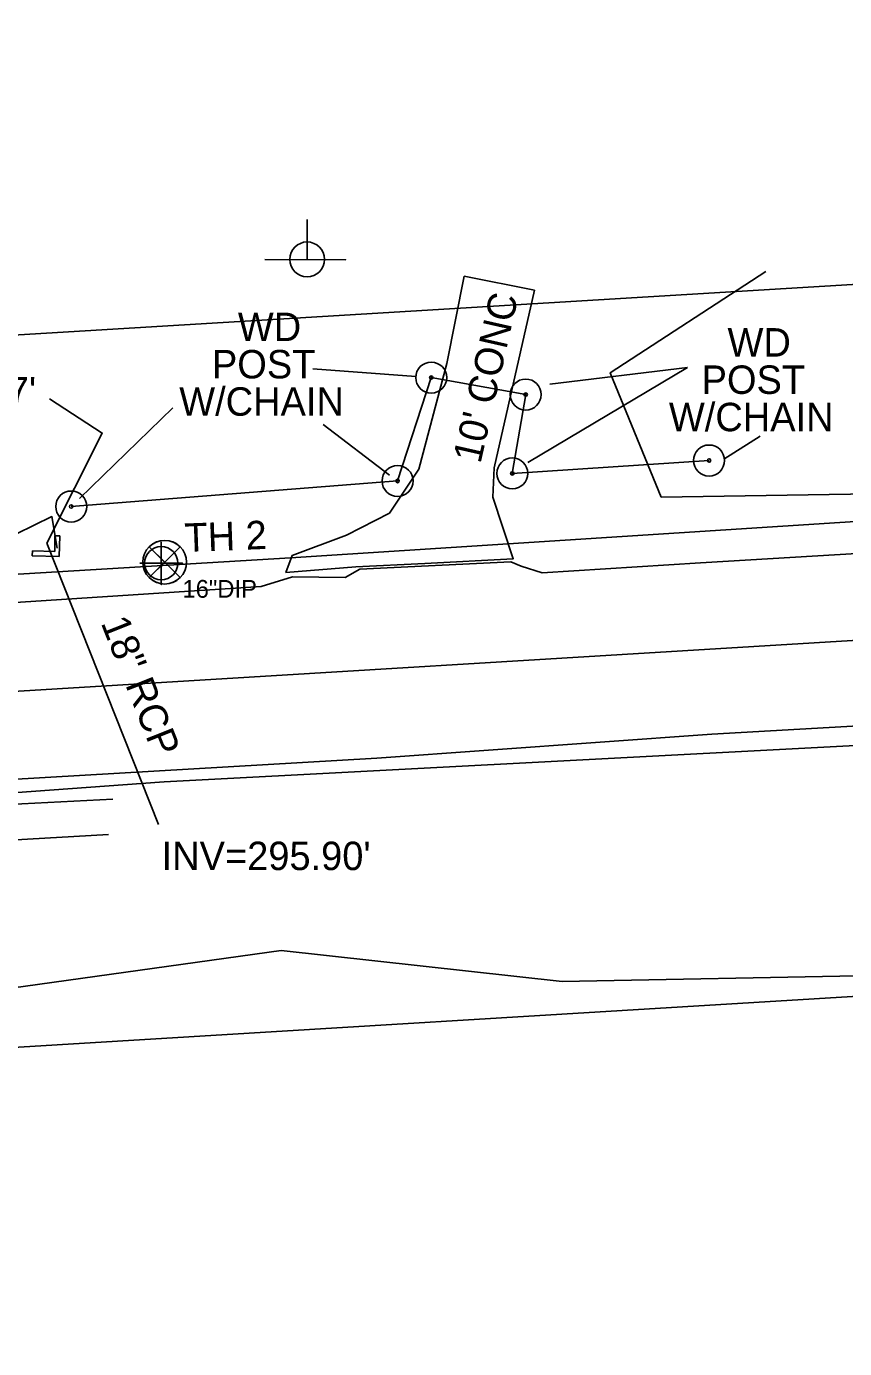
# Model space of a CAD drawing. Extents: x 2110969 to 2113691, y 670003 to 672285.
# Drawn here: x 2112976.4 to 2113091.6, y 670433.2 to 670619.2 of the extents above; entities that cross this region are included whole.
import ezdxf

# ---------------------------------------------------------------- set-up
doc = ezdxf.new("R2010")
doc.units = 0
for name, color, linetype in [('Exist DTM Regular Point CELL', 7, 'Continuous'), ('Exist Horizontal Alignment', 7, 'Continuous'), ('Exist Other Culture Fence Line', 7, 'Continuous'), ('Exist Other Culture Located Object CELL', 7, 'Continuous'), ('Exist Other Culture Located Object Leader', 7, 'Continuous'), ('Exist Other Culture Located Object Text', 7, 'Continuous'), ('Exist Right of Way Line', 7, 'Continuous'), ('Exist Roads EOP', 7, 'Continuous'), ('Exist Roads EOP Other', 7, 'Continuous'), ('Exist Roads EOP Other Text', 7, 'Continuous'), ('Exist Structure Minor Head and End Wall', 7, 'Continuous'), ('Exist Structure Minor Paved Ditch or Gutter', 7, 'Continuous'), ('Exist Structure Minor Pipes RCP 18 Inch', 7, 'Continuous'), ('Exist Structure Minor Pipes RCP 18 Inch Invert', 7, 'Continuous'), ('Exist Structure Minor Pipes RCP 18 Inch Leader', 7, 'Continuous'), ('Exist Structure Minor Pipes RCP 18 Inch Text', 7, 'Continuous'), ('Exist Utilities Power Joint Use Telephone CELL', 7, 'Continuous'), ('Exist Utilities Telephone UG FO SUE LOS B', 7, 'Continuous'), ('Exist Utilities Water Test Hole SUE LOS A CELL', 7, 'Continuous'), ('Exist Utilities Water Test Hole SUE LOS A Cogo Comment', 7, 'Continuous'), ('Exist Utilities Water Test Hole SUE LOS A Text', 7, 'Continuous'), ('Exist Utilities Water UG Line SUE LOS B', 7, 'Continuous'), ('Exist Vegetation Woods Line', 7, 'Continuous')]:
    doc.layers.add(name, color=color, linetype=linetype)

msp = doc.modelspace()

# ---------------------------------------------------------------- linework, layer by layer
at = {"layer": 'Exist DTM Regular Point CELL'}
msp.add_lwpolyline([(2112995.39, 670546.67), (2112995.39, 670540.67), (2112995.39, 670543.67), (2112998.39, 670543.67), (2112992.39, 670543.67)], dxfattribs=at)
msp.add_circle((2112995.39, 670543.67), 2.34, dxfattribs=at)
at = {"layer": 'Exist Horizontal Alignment'}
msp.add_line((2111597.13, 670442.15), (2113362.13, 670549.12), dxfattribs=at)
at = {"layer": 'Exist Other Culture Fence Line'}
msp.add_lwpolyline([(2112982.71, 670551.64), (2113028.65, 670555.23), (2113033.39, 670569.77), (2113046.68, 670567.38), (2113044.8, 670556.3), (2113072.49, 670558.11)], dxfattribs=at)
at = {"layer": 'Exist Other Culture Located Object CELL'}
for centre, radius in [((2113033.39, 670569.77), 2.18), ((2113033.39, 670569.77), 0.24), ((2113046.68, 670567.38), 2.18), ((2113046.68, 670567.38), 0.24), ((2113072.49, 670558.11), 2.18), ((2113028.65, 670555.23), 2.18), ((2113044.8, 670556.3), 2.18), ((2113072.49, 670558.11), 0.24), ((2113044.8, 670556.3), 0.24), ((2112982.71, 670551.64), 2.18), ((2113028.65, 670555.23), 0.24), ((2112982.71, 670551.64), 0.24)]:
    msp.add_circle(centre, radius, dxfattribs=at)
at = {"layer": 'Exist Other Culture Located Object Leader'}
for p, q in [((2113031.21, 670569.94), (2113016.71, 670571.02)), ((2113046.96, 670557.82), (2113069.46, 670571.18)), ((2113050.06, 670568.85), (2113069.46, 670571.18)), ((2112983.89, 670552.78), (2112997, 670565.51)), ((2113027.49, 670556.04), (2113018.18, 670563.18)), ((2113074.58, 670558.29), (2113079.69, 670561.55))]:
    msp.add_line(p, q, dxfattribs=at)
at = {"layer": 'Exist Right of Way Line'}
for p, q in [((2112826.13, 670566.73), (2113691.32, 670619.17)), ((2112275.95, 670433.2), (2113479.86, 670506.17))]:
    msp.add_line(p, q, dxfattribs=at)
at = {"layer": 'Exist Roads EOP'}
for points in [[(2113361.19, 670561.38), (2113300, 670557.8), (2113237.06, 670554.42), (2113180.42, 670550.57), (2113120.04, 670546.64), (2113071.3, 670543.72), (2113048.98, 670542.29), (2113046.06, 670543.23), (2113044.6, 670543.86), (2113023.33, 670542.83), (2113021.27, 670541.64), (2113013.84, 670541.76), (2113009.46, 670540.39), (2112955.35, 670536.89), (2112893.42, 670532.66), (2112858.8, 670530.45), (2112800.17, 670526.96), (2112780.32, 670525.95), (2112776.24, 670526.52)], [(2113362.39, 670537.44), (2113297.78, 670533.58), (2113239.25, 670529.55), (2113180.88, 670526), (2113122.41, 670522.43), (2113072.9, 670519.62), (2113025.73, 670516.23), (2112958.1, 670512.29), (2112895.8, 670508.35), (2112861.36, 670506), (2112803.82, 670502.84), (2112777.04, 670501.11)]]:
    msp.add_lwpolyline(points, dxfattribs=at)
at = {"layer": 'Exist Roads EOP Other'}
msp.add_lwpolyline([(2113038.02, 670584.04), (2113047.91, 670582.05), (2113042.26, 670557.1), (2113042.04, 670552.97), (2113044.92, 670544.3), (2113032.48, 670543.61), (2113022.79, 670543.16), (2113012.94, 670542.38), (2113013.82, 670544.76), (2113021.45, 670547.6), (2113027.51, 670550.72), (2113031.64, 670556.88), (2113035.59, 670571.75), (2113038.02, 670584.04)], dxfattribs=at)
at = {"layer": 'Exist Structure Minor Head and End Wall'}
for p, q in [((2112981.12, 670547.52), (2112980.41, 670547.51)), ((2112980.43, 670545.32), (2112980.41, 670547.51)), ((2112981.12, 670547.52), (2112981.04, 670544.59)), ((2112977.23, 670544.69), (2112977.26, 670545.4)), ((2112977.24, 670544.69), (2112981.04, 670544.59)), ((2112977.26, 670545.4), (2112980.43, 670545.32))]:
    msp.add_line(p, q, dxfattribs=at)
at = {"layer": 'Exist Structure Minor Paved Ditch or Gutter'}
for points in [[(2112886.95, 670541.73), (2112937.79, 670544.35), (2112973.54, 670547.17), (2112975.01, 670547.8), (2112979.99, 670550.22), (2112980.72, 670545.78)], [(2112988.55, 670510.48), (2112937.28, 670507.84), (2112884.19, 670504.54), (2112819.22, 670500.65), (2112761.65, 670497.03), (2112707.07, 670494.25), (2112651.72, 670490.01)], [(2112987.94, 670505.51), (2112937.44, 670502.6), (2112883.37, 670499.77), (2112819.5, 670495.9), (2112761.24, 670491.77), (2112707.32, 670488.73), (2112652.43, 670485.21)]]:
    msp.add_lwpolyline(points, dxfattribs=at)
at = {"layer": 'Exist Structure Minor Pipes RCP 18 Inch'}
msp.add_line((2112979.28, 670546.47), (2112994.98, 670506.91), dxfattribs=at)
at = {"layer": 'Exist Structure Minor Pipes RCP 18 Inch Leader'}
msp.add_lwpolyline([(2112979.28, 670546.47), (2112987.09, 670561.98), (2112979.66, 670566.79)], dxfattribs=at)
at = {"layer": 'Exist Utilities Power Joint Use Telephone CELL'}
msp.add_line((2113015.92, 670586.39), (2113015.92, 670586.39), dxfattribs=at)
msp.add_lwpolyline([(2113009.98, 670586.39), (2113021.32, 670586.35), (2113015.92, 670586.37), (2113015.92, 670592.02)], dxfattribs=at)
msp.add_circle((2113015.92, 670586.4), 2.45, dxfattribs=at)
at = {"layer": 'Exist Utilities Telephone UG FO SUE LOS B'}
msp.add_lwpolyline([(2112667.68, 670491.25), (2112816.71, 670501.11), (2112922.17, 670507.55), (2112995.79, 670512.91), (2113269.89, 670527.3)], dxfattribs=at)
msp.add_lwpolyline([(2112667.68, 670491.25), (2112816.71, 670501.11), (2112922.17, 670507.55), (2112995.79, 670512.91), (2113269.89, 670527.3)], dxfattribs=at)
at = {"layer": 'Exist Utilities Water Test Hole SUE LOS A CELL'}
for points in [[(2112998.04, 670545.99), (2112993.69, 670541.64), (2112995.87, 670543.81), (2112993.69, 670545.99), (2112998.04, 670541.64)], [(2112993.69, 670545.99), (2112995.87, 670543.81), (2112998.04, 670545.99)], [(2112998.04, 670541.64), (2112995.87, 670543.81), (2112993.69, 670541.64)]]:
    msp.add_lwpolyline(points, dxfattribs=at)
msp.add_circle((2112995.87, 670543.81), 3.07, dxfattribs=at)
for start, end in [(45, 135), (225, 315)]:
    msp.add_arc((2112995.87, 670543.81), 3.07, start, end, dxfattribs=at)
at = {"layer": 'Exist Utilities Water UG Line SUE LOS B'}
msp.add_lwpolyline([(2112063.12, 670452.82), (2112061.08, 670490.25), (2112149, 670492.87), (2112291.17, 670500.39), (2112417.24, 670508.2), (2112519.46, 670514.32), (2112696.23, 670524.3), (2112788.03, 670530.3), (2112902.5, 670537.78), (2113013.6, 670544.43), (2113214.88, 670557.36), (2113313.23, 670563.26)], dxfattribs=at)
msp.add_lwpolyline([(2112063.12, 670452.82), (2112061.08, 670490.25), (2112149, 670492.87), (2112291.17, 670500.39), (2112417.24, 670508.2), (2112519.46, 670514.32), (2112696.23, 670524.3), (2112788.03, 670530.3), (2112902.5, 670537.78), (2113013.6, 670544.43), (2113214.88, 670557.36), (2113313.23, 670563.26)], dxfattribs=at)
at = {"layer": 'Exist Vegetation Woods Line'}
for points in [[(2113065.76, 670552.94), (2113058.58, 670570.45), (2113080.47, 670584.69)], [(2113208.9, 670559.59), (2113159.54, 670557.75), (2113116.06, 670553.73), (2113065.76, 670552.94)], [(2113012.26, 670489.19), (2113051.8, 670484.84), (2113095.77, 670485.66), (2113132.41, 670490.56), (2113176.73, 670504.07), (2113233.79, 670515.39), (2113299.62, 670521.41)], [(2112878.84, 670492.06), (2112912.2, 670491.14), (2112940.26, 670479.15), (2113012.26, 670489.19)]]:
    msp.add_lwpolyline(points, dxfattribs=at)

# ---------------------------------------------------------------- texts
at = {"layer": 'Exist Other Culture Located Object Text'}
for s, p in [('WD', (2113006.17, 670574.91)), ('WD', (2113075.09, 670572.73)), ('POST', (2113002.52, 670569.66)), ('POST', (2113071.44, 670567.48)), ('W/CHAIN', (2112997.92, 670564.41)), ('W/CHAIN', (2113066.84, 670562.23))]:
    msp.add_text(s, height=4, dxfattribs=at).set_placement(p)
at = {"layer": 'Exist Roads EOP Other Text'}
msp.add_text("10' CONC", height=4, rotation=77.2369, dxfattribs=at).set_placement((2113040.31, 670557.56))
at = {"layer": 'Exist Structure Minor Pipes RCP 18 Inch Invert'}
for s, p in [("INV=297.07'", (2112948.36, 670565.88)), ("INV=295.90'", (2112995.44, 670500.5))]:
    msp.add_text(s, height=4, dxfattribs=at).set_placement(p)
at = {"layer": 'Exist Structure Minor Pipes RCP 18 Inch Text'}
msp.add_text('18" RCP', height=4, rotation=291.6487, dxfattribs=at).set_placement((2112986.84, 670535.28))
at = {"layer": 'Exist Utilities Water Test Hole SUE LOS A Cogo Comment'}
msp.add_text('16"DIP', height=2.5, dxfattribs=at).set_placement((2112998.37, 670538.81))
at = {"layer": 'Exist Utilities Water Test Hole SUE LOS A Text'}
msp.add_text('TH 2', height=4, rotation=2.1219, dxfattribs=at).set_placement((2112998.73, 670545.25))

doc.saveas('drawing.dxf')
